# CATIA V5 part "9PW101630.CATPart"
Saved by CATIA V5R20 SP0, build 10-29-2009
Part number: 9PW101630
Revision: ANY
Definition: UNKNOWN
Nomenclature: 9PW101630
Source: Unknown
Bounding box of the stored display mesh (mm): x -174.496 to 0, y -14.062 to 5, z -8.1 to 8.1
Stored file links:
  C:\Users\Utente\Desktop\IO LAVORO\3D X SITO CF\CUMSA\3D files PW\pw101630\pw101630_ejection\9PW101630.CATPart
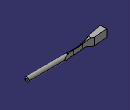
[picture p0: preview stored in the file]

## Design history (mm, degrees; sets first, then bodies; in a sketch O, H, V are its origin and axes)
Body1 "Chaflán4" (main body)
  Solid1: solid without history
